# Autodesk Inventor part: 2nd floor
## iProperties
Created: 2018-12
Part Number: 2nd floor
Document SubType Name: Modeling
Designer: Harindersingh
Density: 1 g/cm^3
Author: Harindersingh
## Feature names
1. Extrusion1
2. Extrusion2
3. Extrusion4
4. Extrusion5
